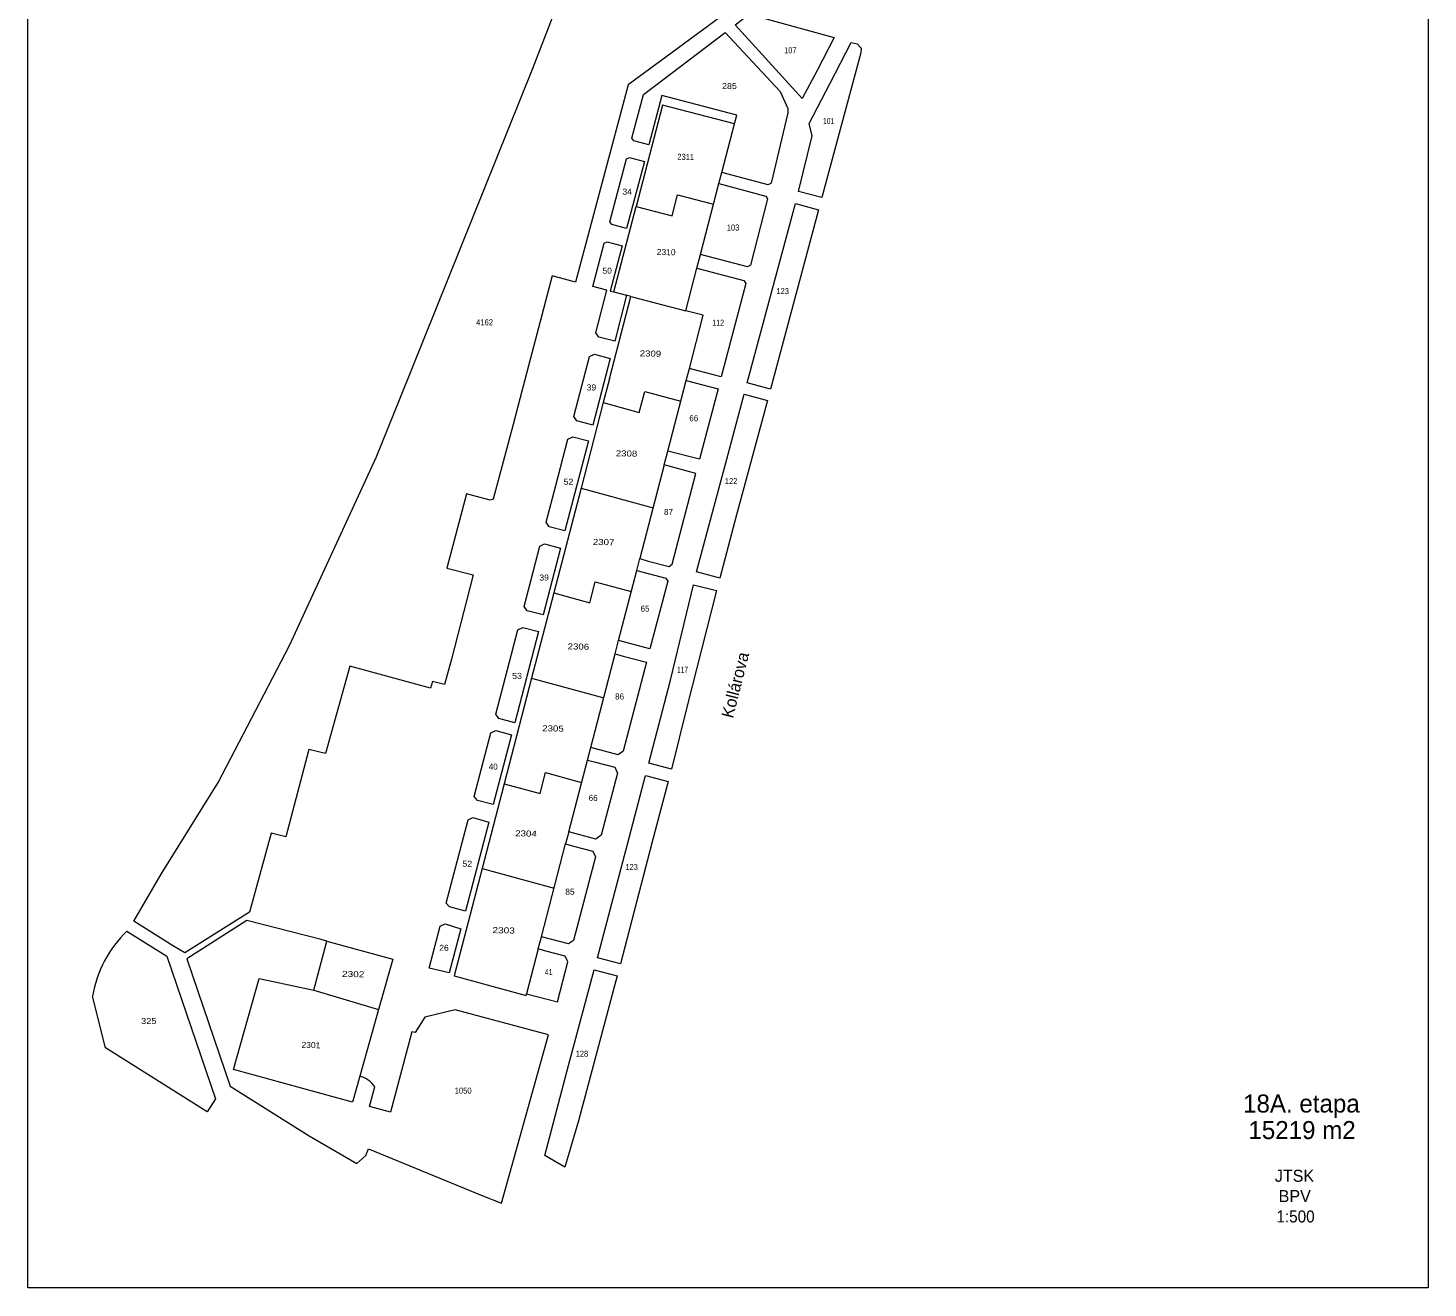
# Model space of a CAD drawing. Extents: x -843556 to -843323, y -1003151 to -1002684.
# Drawn here: x -843555.6 to -843322.7, y -1003151.2 to -1002941.7 of the extents above; entities that cross this region are included whole.
import ezdxf
from ezdxf.enums import TextEntityAlignment as Align

# ---------------------------------------------------------------- set-up
doc = ezdxf.new("R2010")
doc.units = 0
doc.header["$LTSCALE"] = 0.4
doc.layers.add('20', color=7, linetype='Continuous')
for name, color, linetype, lineweight in [('35', 7, 'Continuous', 13), ('38', 7, 'Continuous', 13), ('43', 7, 'Continuous', 13), ('44', 7, 'Continuous', 13)]:
    doc.layers.add(name, color=color, linetype=linetype, lineweight=lineweight)

msp = doc.modelspace()

# ---------------------------------------------------------------- linework, layer by layer
at = {"layer": '38'}
for p, q in [((-843440.623, -1002967.521), (-843440.147, -1002965.694)), ((-843444.292, -1002981.61), (-843443.703, -1002979.347)), ((-843455.26, -1002986.3), (-843455.994, -1002986.108)), ((-843446.056, -1003000.264), (-843445.539, -1002998.272)), ((-843449.715, -1003014.322), (-843449.114, -1003012.014)), ((-843454.294, -1003031.91), (-843453.772, -1003029.906)), ((-843457.898, -1003045.742), (-843457.322, -1003043.534)), ((-843462.511, -1003063.419), (-843461.962, -1003061.318)), ((-843465.62, -1003075.357), (-843466.142, -1003077.364)), ((-843470.692, -1003094.842), (-843470.165, -1003092.82))]:
    msp.add_line(p, q, dxfattribs=at)
for points in [[(-843438.03, -1002957.58), (-843450.03, -1002954.46), (-843454.42, -1002971.33)], [(-843458.13, -1002985.55), (-843454.42, -1002971.33), (-843448.43, -1002972.89), (-843447.52, -1002969.4), (-843441.519, -1002970.96)], [(-843458.829, -1003000), (-843455.26, -1002986.3), (-843446.13, -1002988.67)], [(-843458.829, -1003000), (-843459.86, -1003003.96), (-843453.87, -1003005.59), (-843452.96, -1003002.11), (-843446.96, -1003003.74)], [(-843459.86, -1003003.96), (-843463.56, -1003018.18), (-843451.57, -1003021.45)], [(-843463.56, -1003018.18), (-843468.09, -1003035.61), (-843462.1, -1003037.24), (-843461.19, -1003033.76), (-843455.2, -1003035.39)], [(-843468.09, -1003035.61), (-843471.78, -1003049.81), (-843459.8, -1003053.04)], [(-843471.78, -1003049.81), (-843476.35, -1003067.35), (-843470.36, -1003068.98), (-843469.45, -1003065.5), (-843463.48, -1003067.13)], [(-843476.35, -1003067.35), (-843480.02, -1003081.44), (-843468.05, -1003084.7)], [(-843480.02, -1003081.44), (-843484.67, -1003099.29), (-843472.7, -1003102.55), (-843472.629, -1003102.278)], [(-843505.83, -1003093.52), (-843494.89, -1003096.54), (-843497.27, -1003104.88)], [(-843507.99, -1003101.69), (-843497.27, -1003104.88), (-843500.363, -1003115.985)]]:
    msp.add_lwpolyline(points, dxfattribs=at)
at = {"layer": '43'}
msp.add_line((-843498.765, -1003121.057), (-843497.853, -1003117.783), dxfattribs=at)
for points in [[(-843438.29, -1002938.313), (-843448.413, -1002945.721), (-843455.72, -1002951.13), (-843464.46, -1002983.94), (-843468.34, -1002982.89), (-843473.73, -1003003.32), (-843474.83, -1003007.61), (-843478.154, -1003020.042), (-843478.7, -1003020.16), (-843482.602, -1003019.13), (-843485.861, -1003031.481), (-843481.959, -1003032.511), (-843481.527, -1003032.618), (-843485.13, -1003046.65), (-843486.27, -1003050.84), (-843488.29, -1003050.34), (-843488.61, -1003051.48), (-843502.02, -1003047.82), (-843506.07, -1003062.31), (-843508.84, -1003061.64), (-843512.69, -1003076.21), (-843515.09, -1003075.57), (-843518.74, -1003088.692), (-843529.457, -1003095.49), (-843531.363, -1003094.376), (-843537.941, -1003090.241), (-843533.43, -1003082.38), (-843523.93, -1003067.16), (-843512.07, -1003044.38), (-843497.62, -1003013.1), (-843493.65, -1003003.22), (-843471.66, -1002948.47), (-843448.4, -1002888.465)], [(-843500.363, -1003115.985), (-843501.57, -1003120.32), (-843521.37, -1003114.91), (-843517.12, -1003099.75), (-843507.99, -1003101.69), (-843505.83, -1003093.52), (-843506.77, -1003093.29), (-843519.14, -1003090.13), (-843529.126, -1003096.464), (-843521.91, -1003117.64), (-843508.77, -1003125.9), (-843500.85, -1003130.54), (-843499.35, -1003129.17), (-843498.891, -1003128.061), (-843480.151, -1003135.811), (-843476.79, -1003137.12), (-843468.971, -1003109.142), (-843484.5, -1003104.94), (-843489.57, -1003106.17), (-843491.15, -1003108.75), (-843491.73, -1003108.6), (-843495.249, -1003121.982), (-843498.765, -1003121.057)], [(-843539.102, -1003091.854), (-843532.438, -1003096.043), (-843524.358, -1003119.756), (-843525.733, -1003121.944)], [(-843525.733, -1003121.944), (-843542.65, -1003111.31), (-843544.828, -1003102.668)]]:
    msp.add_lwpolyline(points, dxfattribs=at)
for points in [[(-843437.935, -1002941.144), (-843435.58, -1002939.36), (-843424.49, -1002942.38), (-843421.44, -1002943.21), (-843424.311, -1002948.699), (-843426.76, -1002953.38), (-843430.664, -1002949.105)], [(-843452.275, -1002961.069), (-843454.772, -1002960.409), (-843455.1, -1002959.99), (-843453.17, -1002952.685), (-843439.584, -1002942.393), (-843430.45, -1002952.23), (-843429.15, -1002955.06), (-843429.18, -1002955.74), (-843431.921, -1002967.448), (-843432.412, -1002967.744), (-843440.147, -1002965.694), (-843438.03, -1002957.58), (-843437.67, -1002956.142), (-843450.119, -1002952.879)], [(-843425.62, -1002957.53), (-843422.16, -1002950.91), (-843418.61, -1002944.04), (-843417.63, -1002944.3), (-843416.98, -1002945.01), (-843417.01, -1002945.78), (-843419.3, -1002954.2), (-843423.52, -1002969.87), (-843427.365, -1002968.838), (-843425.12, -1002959.61)], [(-843455.986, -1002974.981), (-843458.45, -1002974.33), (-843458.778, -1002973.911), (-843456.006, -1002963.417), (-843455.513, -1002963.215), (-843453.008, -1002963.877)], [(-843443.703, -1002979.347), (-843440.623, -1002967.521), (-843432.833, -1002969.598), (-843432.547, -1002970.084), (-843435.377, -1002981.093), (-843435.866, -1002981.38)], [(-843427.905, -1002970.851), (-843424.06, -1002971.882), (-843432.066, -1003001.719), (-843435.911, -1003000.687)], [(-843459.248, -1002985.255), (-843461.61, -1002984.63), (-843459.708, -1002977.43), (-843459.216, -1002977.228), (-843456.71, -1002977.89), (-843458.702, -1002985.398), (-843458.13, -1002985.55), (-843455.994, -1002986.108), (-843457.945, -1002993.762), (-843460.604, -1002993.065), (-843461.106, -1002992.342)], [(-843445.539, -1002998.272), (-843443.24, -1002989.43), (-843446.13, -1002988.67), (-843444.292, -1002981.61), (-843441.984, -1002982.215), (-843436.462, -1002983.662), (-843436.176, -1002984.15), (-843440.242, -1002999.659), (-843444.09, -1002998.65)], [(-843461.624, -1003007.687), (-843464.256, -1003006.997), (-843464.758, -1003006.274), (-843462.143, -1002996.296), (-843461.351, -1002995.912), (-843458.711, -1002996.604)], [(-843449.114, -1003012.014), (-843446.056, -1003000.264), (-843440.775, -1003001.695), (-843443.84, -1003013.388)], [(-843436.419, -1003002.58), (-843432.574, -1003003.611), (-843437.683, -1003022.652), (-843440.5, -1003033.15), (-843444.345, -1003032.118), (-843439.095, -1003012.552)], [(-843466.233, -1003025.288), (-843468.87, -1003024.597), (-843469.371, -1003023.874), (-843467.769, -1003017.76), (-843465.742, -1003010.029), (-843464.95, -1003009.645), (-843462.307, -1003010.338)], [(-843453.772, -1003029.906), (-843452.389, -1003030.309), (-843448.927, -1003031.217), (-843448.407, -1003030.809), (-843444.456, -1003015.737), (-843449.715, -1003014.322)], [(-843469.876, -1003039.285), (-843472.537, -1003038.587), (-843473.039, -1003037.864), (-843470.413, -1003027.847), (-843469.621, -1003027.464), (-843466.974, -1003028.157)], [(-843452.1, -1003044.896), (-843457.322, -1003043.534), (-843454.294, -1003031.91), (-843449.441, -1003033.176), (-843449.155, -1003033.664)], [(-843452.287, -1003063.937), (-843448.68, -1003050.11), (-843444.863, -1003034.266), (-843441.028, -1003035.237), (-843445.9, -1003054.42), (-843448.543, -1003064.916)], [(-843474.593, -1003057.207), (-843477.237, -1003056.518), (-843477.739, -1003055.795), (-843475.792, -1003048.369), (-843474.058, -1003041.752), (-843473.266, -1003041.368), (-843470.626, -1003042.06)], [(-843461.962, -1003061.318), (-843457.898, -1003045.742), (-843456.533, -1003046.12), (-843452.685, -1003047.129), (-843456.561, -1003061.915), (-843457.406, -1003062.533)], [(-843478.16, -1003070.818), (-843480.804, -1003070.125), (-843481.331, -1003069.499), (-843478.555, -1003058.909), (-843477.763, -1003058.525), (-843475.117, -1003059.218)], [(-843462.511, -1003063.419), (-843461.163, -1003063.783), (-843457.954, -1003064.624), (-843457.521, -1003065.578), (-843460.233, -1003075.927), (-843461.08, -1003076.55), (-843465.62, -1003075.357)], [(-843457.025, -1003097.319), (-843460.852, -1003096.297), (-843455.848, -1003077.409), (-843452.82, -1003065.98), (-843449.078, -1003066.959), (-843451.706, -1003077.001)], [(-843482.805, -1003088.538), (-843485.449, -1003087.845), (-843485.976, -1003087.219), (-843482.337, -1003073.337), (-843481.545, -1003072.953), (-843478.927, -1003073.743)], [(-843466.142, -1003077.364), (-843464.82, -1003077.733), (-843461.61, -1003078.574), (-843461.168, -1003079.492), (-843464.819, -1003093.421), (-843465.655, -1003094.003), (-843470.165, -1003092.82)], [(-843485.495, -1003098.801), (-843488.811, -1003098.035), (-843486.985, -1003091.067), (-843486.193, -1003090.683), (-843483.574, -1003091.473)], [(-843472.629, -1003102.278), (-843467.493, -1003103.623), (-843465.752, -1003096.981), (-843466.185, -1003096.027), (-843469.395, -1003095.186), (-843470.692, -1003094.842)], [(-843464, -1003123.45), (-843466.24, -1003131.13), (-843469.59, -1003129.165), (-843465.64, -1003114.21), (-843461.38, -1003098.29), (-843457.557, -1003099.311)]]:
    msp.add_lwpolyline(points, close=True, dxfattribs=at)
for centre, radius, start, end in [((-843525.208, -1003106.1342), 19.9241, 134.21357, 169.98024), ((-843501.57, -1003120.32), 4.5, 34.31865, 74.43762)]:
    msp.add_arc(centre, radius, start, end, dxfattribs=at)
at = {"layer": '44'}
msp.add_lwpolyline([(-843322.682, -1002683.578), (-843322.682, -1003151.23), (-843555.557, -1003151.23), (-843555.557, -1002683.578)], close=True, dxfattribs=at)

# ---------------------------------------------------------------- texts
at = {"layer": '20'}
msp.add_text('Kollárova', height=2, rotation=75.846, dxfattribs=at).set_placement((-843438.311, -1003056.567))
at = {"layer": '35'}
for s, width, p in [('2311', 0.9, (-843446.164, -1002963.5883)), ('2310', 1.05, (-843449.412, -1002979.4292)), ('2309', 1.2, (-843452.0315, -1002996.2947)), ('2308', 1.2, (-843456.0095, -1003012.9189)), ('2307', 1.2, (-843459.818, -1003027.6612)), ('2306', 1.2, (-843464.0175, -1003045.0387)), ('2305', 1.2, (-843468.2385, -1003058.6523)), ('2304', 1.2, (-843472.7315, -1003076.1277)), ('2303', 1.25, (-843476.443, -1003092.2368)), ('2302', 1.25, (-843501.4725, -1003099.5157)), ('2301', 1.05, (-843508.506, -1003111.3162))]:
    msp.add_text(s, height=1, rotation=358.734, dxfattribs=dict(at, width=width)).set_placement(p, align=Align.CENTER)
at = {"layer": '43'}
for s, width, p in [('107', 0.85, (-843429.778, -1002945.848)), ('285', 1.1, (-843440.107, -1002951.801)), ('101', 0.65, (-843423.289, -1002957.62)), ('34', 1.05, (-843456.673, -1002969.374)), ('103', 0.9, (-843439.314, -1002975.339)), ('50', 1.05, (-843459.997, -1002982.508)), ('123', 0.9, (-843431.065, -1002985.917)), ('4162', 0.95, (-843481.02, -1002991.111)), ('112', 0.7, (-843441.729, -1002991.171)), ('39', 1.05, (-843462.618, -1003001.943)), ('52', 1.1, (-843466.472, -1003017.621)), ('122', 0.9, (-843439.642, -1003017.511)), ('39', 1.05, (-843470.489, -1003033.553)), ('117', 0.65, (-843447.582, -1003048.908)), ('53', 1.1, (-843475.033, -1003049.916)), ('52', 1.1, (-843483.305, -1003081.158)), ('123', 0.9, (-843456.185, -1003081.696)), ('85', 1.05, (-843466.192, -1003085.813)), ('26', 1.05, (-843487.146, -1003095.147)), ('41', 0.7, (-843469.6, -1003099.17)), ('325', 1.15, (-843536.747, -1003107.329)), ('128', 0.9, (-843464.451, -1003112.767)), ('1050', 0.95, (-843484.594, -1003118.9))]:
    msp.add_text(s, height=1, dxfattribs=dict(at, width=width)).set_placement(p)
for s, p in [('66', (-843445.553, -1003007.066)), ('87', (-843449.763, -1003022.652)), ('65', (-843453.666, -1003038.724)), ('86', (-843457.897, -1003053.339)), ('40', (-843478.917, -1003065.007)), ('66', (-843462.297, -1003070.208))]:
    msp.add_text(s, height=1, dxfattribs=at).set_placement(p)
at = {"layer": '44'}
for s, height, p in [('18A. etapa', 3, (-843353.442, -1003122.043)), ('15219 m2', 3, (-843352.553, -1003126.462)), ('JTSK', 2, (-843348.16, -1003133.568)), ('BPV', 2, (-843347.526, -1003136.943))]:
    msp.add_text(s, height=height, dxfattribs=at).set_placement(p)
at = {"layer": '44', "width": 0.95}
msp.add_text('1:500', height=2, dxfattribs=at).set_placement((-843347.897, -1003140.331))

doc.saveas('drawing.dxf')
